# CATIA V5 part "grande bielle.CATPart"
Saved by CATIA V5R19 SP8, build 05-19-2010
Part number: grande bielle
Bounding box of the stored display mesh (mm): x -10 to 0, y -2.965 to 2.965, z -48.824 to -11.176
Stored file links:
  C:\Users\rcousturie\Desktop\EU_thinkMotion\iao\IAO_MMS_Groupe1\glenerrant\glenerrant\Nouveau dossier\grande bielle.CATPart
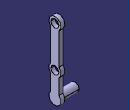
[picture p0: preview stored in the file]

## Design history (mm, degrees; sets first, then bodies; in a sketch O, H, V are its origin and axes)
Set1
  Point1: (0, 0, -14)
  Point2: (0, 0, -34)
  Point3: (0, 0, -46)
Body1 (main body)
  Line1 to Line5: stored without definition
  Sketch1 on yz-plane, origin (0, 0, 0), H (0, 1, 0), V (0, 0, 1)
    point P1 (110, 0)
    arc A1 centre (0, -34) radius 3 from (2, -36.2361) to (2, -31.7639) ccw
    point P2 (0, -34)
    arc A2 centre (0, -46) radius 3 from (-2, -43.7639) to (2, -43.7639) ccw
    point P3 (0, -46)
    arc A3 centre (0, -14) radius 3 from (2, -16.2361) to (-2, -16.2361) ccw
    point P4 (0, -14)
    reference projected point E1 (0, -34) from Point2
    reference projected point E2 (0, -14) from Point1
    reference projected point E3 (0, -46) from Point3
    line L1 (2, -43.7639) -> (2, -36.2361)
    line L2 (-2, -36.2361) -> (-2, -43.7639)
    line L3 (-2, -31.7639) -> (-2, -16.2361)
    point P9 (-2, -31.7639)
    line L4 (2, -16.2361) -> (2, -31.7639)
    reference projected line E4 (0, -14) -> (0, -46) from Line1
    reference projected line E5 (0, -14) -> (0, -46) from Line1
    reference projected line E6 (0, -14) -> (0, -46) from Line2
    reference projected line E7 (0, -14) -> (0, -46) from Line2
    reference projected line E8 (0, -14) -> (0, -46) from Line3
    reference projected line E9 (0, -14) -> (0, -46) from Line5
    arc A4 centre (0, -34) radius 3 from (-2, -31.7639) to (-2, -36.2361) ccw
    circle A5 centre (0, -14) radius 2
    point P13 (0, -14)
    circle A6 centre (0, -34) radius 2
    point P14 (0, -34)
    reference projected point E10 (0, -14) from Point1
    reference projected point E11 (0, -34) from Point2
    radius A3 = 3
    radius A1 = 3
    radius A2 = 3
    distance L4 E8 = 2
    distance L1 E9 = 2
    radius A6 = 2
    radius A5 = 2
    coincidence: P2 E1, E2 P4, E3 P3, P9 A1, A1 A4, E10 P13, E11 P14
    vertical: L4 V
    symmetry: L1 L2 E4, L3 L4 E7
    parallelism: L1 L2, L2 E5, L3 L4, L4 E6
  Pad1: profile Sketch1, direction (1, 0, 0), length 0, opposite side length 2
  Sketch2 on start face of Pad1, origin (-2, 0, 0), H (0, -1, 0), V (0, 0, 1)
    circle A1 centre (0, -46) radius 2
    point P1 (0, -46)
    reference projected point E1 (0, -46) from Point3
    radius A1 = 2
    coincidence: P1 E1
  Pad2: profile Sketch2, direction (-1, 0, 0), length 8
